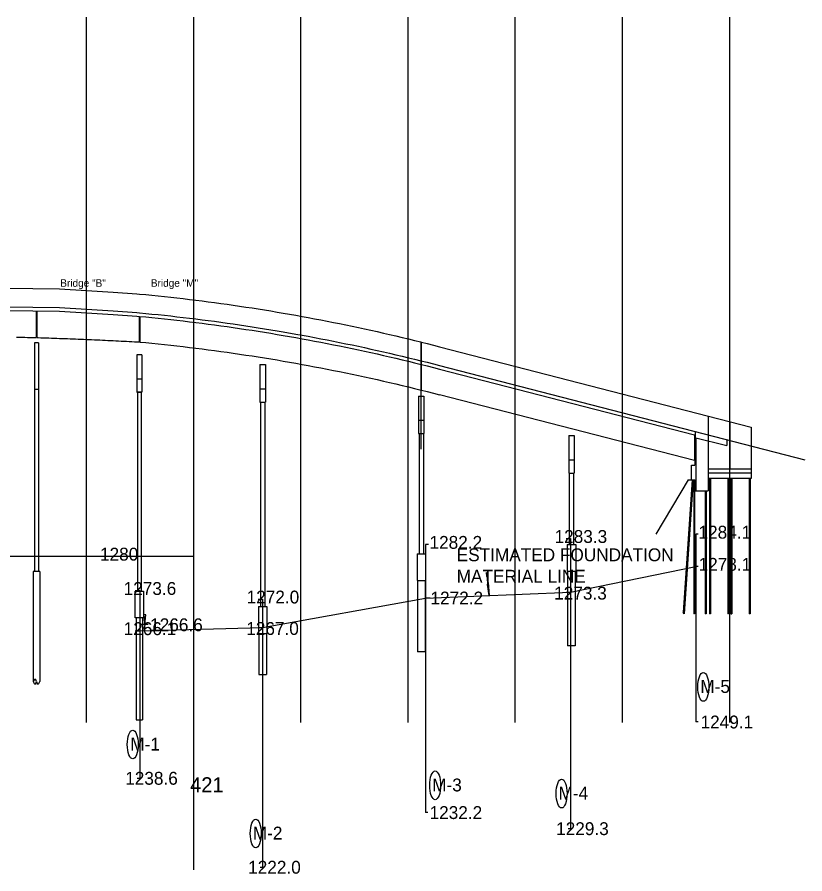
# Model space of a CAD drawing. Extents: x 2144454 to 2150191, y 137247 to 142100.
# Drawn here: x 2144990 to 2145724, y 137247 to 138047 of the extents above; entities that cross this region are included whole.
import ezdxf

# ---------------------------------------------------------------- set-up
doc = ezdxf.new("R2010")
doc.units = 0
for name, color, linetype in [('11', 7, 'Continuous'), ('3A', 7, 'Continuous'), ('BORE', 7, 'Continuous'), ('FinGrade', 7, 'Continuous'), ('PR_Align_Ramp_M_Txt', 7, 'Continuous'), ('PR_Bridge', 7, 'Continuous'), ('PR_Bridge_Pier', 7, 'Continuous'), ('PR_Bridge_Piling', 7, 'Continuous'), ('PR_Bridge_Slope_Wall', 7, 'Continuous'), ('T_BORE', 7, 'Continuous'), ('TOPO_Wall Retaining', 7, 'Continuous'), ('XSEC_Section_Grid_Major', 7, 'Continuous')]:
    doc.layers.add(name, color=color, linetype=linetype)

msp = doc.modelspace()

# ---------------------------------------------------------------- linework, layer by layer
at = {"layer": '11'}
for p, q in [((2145505.82, 137510.15), (2145622.49, 137534.15)), ((2145218.58, 137477.15), (2145370.38, 137504.65)), ((2145370.38, 137504.65), (2145505.82, 137510.15)), ((2145103.88, 137474.15), (2145218.58, 137477.15))]:
    msp.add_line(p, q, dxfattribs=at)
at = {"layer": '3A'}
msp.add_line((2145366.56, 137643.65), (2145366.56, 137711.69), dxfattribs=at)
at = {"layer": 'BORE'}
for p, q in [((2145501.53, 137560.15), (2145505.82, 137560.15)), ((2145505.82, 137560.15), (2145505.82, 137289.65)), ((2145624.76, 137564.15), (2145622.49, 137564.15)), ((2145622.49, 137564.15), (2145622.49, 137389.15)), ((2145370.38, 137554.65), (2145370.38, 137304.65)), ((2145373.36, 137554.65), (2145370.38, 137554.65)), ((2145370.38, 137554.65), (2145370.38, 137304.65)), ((2145624.76, 137534.15), (2145622.49, 137534.15)), ((2145099.59, 137511.65), (2145103.88, 137511.65)), ((2145103.88, 137511.65), (2145103.88, 137336.65)), ((2145374.67, 137504.65), (2145370.38, 137504.65)), ((2145501.53, 137510.15), (2145505.82, 137510.15)), ((2145214.29, 137503.65), (2145218.58, 137503.65)), ((2145218.58, 137503.65), (2145218.58, 137253.65)), ((2145099.59, 137474.15), (2145103.88, 137474.15)), ((2145214.29, 137477.15), (2145218.58, 137477.15)), ((2145624.89, 137389.15), (2145622.49, 137389.15)), ((2145101.48, 137336.65), (2145103.88, 137336.65)), ((2145372.78, 137304.65), (2145370.38, 137304.65)), ((2145372.78, 137304.65), (2145370.38, 137304.65)), ((2145372.78, 137304.65), (2145370.38, 137304.65)), ((2145503.42, 137289.65), (2145505.82, 137289.65)), ((2145216.18, 137253.65), (2145218.58, 137253.65))]:
    msp.add_line(p, q, dxfattribs=at)
at = {"layer": 'Defpoints'}
for p, q in [((2144454.23, 137543.65), (2145154.23, 137543.65)), ((2144999.91, 137543.65), (2145154.23, 137543.65)), ((2145154.23, 137391.15), (2145154.23, 137543.65)), ((2145154.23, 137251.15), (2145154.23, 137543.65)), ((2145111.85, 137480.13), (2145105.2, 137480.13)), ((2145110.19, 137476.69), (2145106.86, 137476.69))]:
    msp.add_line(p, q, dxfattribs=at)
msp.add_lwpolyline([(2145108.53, 137480.13), (2145109.57, 137489.14), (2145107.49, 137489.14)], close=True, dxfattribs=at)
at = {"layer": 'FinGrade'}
for p, q in [((2144979.23, 137776.3), (2145004.23, 137776.13)), ((2145004.23, 137776.13), (2145029.23, 137775.65)), ((2145029.23, 137775.65), (2145054.23, 137774.16)), ((2145054.23, 137774.16), (2145079.23, 137772.52)), ((2145079.23, 137772.52), (2145101.27, 137771.01)), ((2145101.27, 137771.01), (2145103.67, 137770.78)), ((2145383.67, 137721.65), (2145724.3, 137633.7))]:
    msp.add_line(p, q, dxfattribs=at)
msp.add_lwpolyline([(2145103.67, 137770.78), (2145109.51, 137770.23), (2145115.34, 137769.66), (2145121.17, 137769.07), (2145127.01, 137768.46), (2145132.84, 137767.83), (2145138.67, 137767.18), (2145144.51, 137766.51), (2145150.34, 137765.81), (2145156.17, 137765.1), (2145162.01, 137764.37), (2145167.84, 137763.62), (2145173.67, 137762.85), (2145179.51, 137762.05), (2145185.34, 137761.24), (2145191.17, 137760.41), (2145197.01, 137759.56), (2145202.84, 137758.68), (2145208.67, 137757.79), (2145214.51, 137756.88), (2145220.34, 137755.94), (2145226.17, 137754.99), (2145232.01, 137754.02), (2145237.84, 137753.02), (2145249.51, 137750.98), (2145255.34, 137749.92), (2145261.17, 137748.85), (2145267.01, 137747.76), (2145272.84, 137746.64), (2145278.67, 137745.51), (2145284.51, 137744.35), (2145290.34, 137743.18), (2145296.17, 137741.98), (2145302.01, 137740.77), (2145307.84, 137739.54), (2145313.67, 137738.28), (2145319.51, 137737.01), (2145325.34, 137735.71), (2145331.17, 137734.4), (2145337.01, 137733.06), (2145342.84, 137731.7), (2145348.67, 137730.33), (2145354.51, 137728.93), (2145360.34, 137727.52), (2145366.17, 137726.08), (2145372.01, 137724.63), (2145377.84, 137723.15), (2145383.67, 137721.65)], dxfattribs=at)
at = {"layer": 'PR_Bridge'}
for p, q in [((2144979.23, 137793.8), (2145004.23, 137793.63)), ((2145004.23, 137793.63), (2145029.23, 137793.15)), ((2145029.23, 137793.15), (2145054.23, 137791.66)), ((2145054.23, 137791.66), (2145079.23, 137790.02)), ((2145079.23, 137790.02), (2145101.27, 137788.51)), ((2145101.27, 137788.51), (2145103.67, 137788.28)), ((2144979.23, 137772.96), (2145004.23, 137772.79)), ((2145004.23, 137772.79), (2145029.23, 137772.32)), ((2145007.3, 137772.74), (2145007.3, 137747.68)), ((2145007.97, 137772.72), (2145007.97, 137747.66)), ((2145029.23, 137772.32), (2145054.23, 137770.83)), ((2145054.23, 137770.83), (2145079.23, 137769.18)), ((2145079.23, 137769.18), (2145101.27, 137767.67)), ((2145101.27, 137767.67), (2145103.67, 137767.45)), ((2145103.24, 137767.36), (2145103.24, 137743.58)), ((2145103.24, 137767.31), (2145103.24, 137743.57)), ((2145103.91, 137767.29), (2145103.91, 137743.51)), ((2145101.27, 137743.76), (2145103.24, 137743.57)), ((2145366.49, 137722.67), (2145366.49, 137743.5)), ((2145366.66, 137722.63), (2145366.66, 137743.46)), ((2145383.67, 137739.15), (2145674.23, 137664.13)), ((2145366.41, 137698.77), (2145366.41, 137722.69)), ((2145366.74, 137698.69), (2145366.74, 137722.61)), ((2145383.67, 137718.32), (2145621.23, 137656.98)), ((2145383.67, 137694.55), (2145621.23, 137633.21)), ((2145634.23, 137674.46), (2145634.23, 137656.96)), ((2145654.23, 137669.29), (2145654.23, 137651.79)), ((2145674.23, 137664.13), (2145674.23, 137646.63)), ((2145621.23, 137656.97), (2145621.23, 137633.21)), ((2145622.31, 137654.06), (2145622.31, 137660.03)), ((2145621.23, 137654.32), (2145651.57, 137647.06)), ((2145621.23, 137654.32), (2145622.31, 137654.06)), ((2145621.56, 137654.24), (2145621.56, 137628.56)), ((2145622.56, 137654), (2145622.56, 137604.86)), ((2145651.57, 137652.48), (2145651.57, 137647.06)), ((2145618.56, 137628.56), (2145621.56, 137628.56)), ((2145618.56, 137614.86), (2145618.56, 137628.56)), ((2145618.56, 137614.86), (2145621.56, 137614.86)), ((2145621.56, 137614.86), (2145621.56, 137604.86)), ((2145621.56, 137604.86), (2145622.56, 137604.86))]:
    msp.add_line(p, q, dxfattribs=at)
for points in [[(2145103.67, 137788.28), (2145109.51, 137787.73), (2145115.34, 137787.16), (2145121.17, 137786.57), (2145127.01, 137785.96), (2145132.84, 137785.33), (2145138.67, 137784.68), (2145144.51, 137784.01), (2145150.34, 137783.31), (2145156.17, 137782.6), (2145162.01, 137781.87), (2145167.84, 137781.12), (2145173.67, 137780.35), (2145179.51, 137779.55), (2145185.34, 137778.74), (2145191.17, 137777.91), (2145197.01, 137777.06), (2145202.84, 137776.18), (2145208.67, 137775.29), (2145214.51, 137774.38), (2145220.34, 137773.44), (2145226.17, 137772.49), (2145232.01, 137771.52), (2145237.84, 137770.52), (2145249.51, 137768.48), (2145255.34, 137767.42), (2145261.17, 137766.35), (2145267.01, 137765.26), (2145272.84, 137764.14), (2145278.67, 137763.01), (2145284.51, 137761.85), (2145290.34, 137760.68), (2145296.17, 137759.48), (2145302.01, 137758.27), (2145307.84, 137757.04), (2145313.67, 137755.78), (2145319.51, 137754.51), (2145325.34, 137753.21), (2145331.17, 137751.9), (2145337.01, 137750.56), (2145342.84, 137749.2), (2145348.67, 137747.83), (2145354.51, 137746.43), (2145360.34, 137745.02), (2145366.17, 137743.58), (2145366.49, 137743.5)], [(2145103.67, 137767.45), (2145109.51, 137766.9), (2145115.34, 137766.33), (2145121.17, 137765.74), (2145127.01, 137765.13), (2145132.84, 137764.5), (2145138.67, 137763.84), (2145144.51, 137763.17), (2145150.34, 137762.48), (2145156.17, 137761.77), (2145162.01, 137761.04), (2145167.84, 137760.28), (2145173.67, 137759.51), (2145179.51, 137758.72), (2145185.34, 137757.91), (2145191.17, 137757.08), (2145197.01, 137756.22), (2145202.84, 137755.35), (2145208.67, 137754.46), (2145214.51, 137753.54), (2145220.34, 137752.61), (2145226.17, 137751.66), (2145232.01, 137750.68), (2145237.84, 137749.69), (2145249.51, 137747.64), (2145255.34, 137746.59), (2145261.17, 137745.52), (2145267.01, 137744.42), (2145272.84, 137743.31), (2145278.67, 137742.17), (2145284.51, 137741.02), (2145290.34, 137739.85), (2145296.17, 137738.65), (2145302.01, 137737.44), (2145307.84, 137736.2), (2145313.67, 137734.95), (2145319.51, 137733.67), (2145325.34, 137732.38), (2145331.17, 137731.06), (2145337.01, 137729.73), (2145342.84, 137728.37), (2145348.67, 137727), (2145354.51, 137725.6), (2145360.34, 137724.18), (2145366.49, 137722.67)], [(2144989.1, 137748.15), (2144991.6, 137748.09), (2144994.1, 137748.03), (2144996.6, 137747.97), (2144999.1, 137747.9), (2145001.6, 137747.84), (2145004.1, 137747.77), (2145006.6, 137747.7), (2145007.3, 137747.68)], [(2145007.97, 137747.66), (2145009.09, 137747.63), (2145011.59, 137747.55), (2145014.09, 137747.48), (2145016.59, 137747.4), (2145019.09, 137747.32), (2145021.59, 137747.24), (2145024.09, 137747.16), (2145026.59, 137747.07), (2145029.09, 137746.98), (2145031.59, 137746.9), (2145034.09, 137746.8), (2145036.59, 137746.71), (2145039.08, 137746.62), (2145041.58, 137746.52), (2145044.08, 137746.42), (2145046.58, 137746.33), (2145049.08, 137746.22), (2145051.58, 137746.12), (2145054.08, 137746.02), (2145056.58, 137745.91), (2145059.08, 137745.8), (2145061.58, 137745.69), (2145064.08, 137745.58), (2145066.58, 137745.46), (2145069.08, 137745.35), (2145071.57, 137745.23), (2145074.07, 137745.11), (2145076.57, 137744.99), (2145079.07, 137744.86), (2145081.57, 137744.74), (2145084.07, 137744.61), (2145086.57, 137744.48), (2145089.07, 137744.35), (2145091.57, 137744.22), (2145094.07, 137744.08), (2145096.57, 137743.95), (2145099.07, 137743.81), (2145101.56, 137743.67), (2145103.24, 137743.57)], [(2145102.42, 137743.65), (2145103.24, 137743.58)], [(2145103.91, 137743.51), (2145109.51, 137742.98), (2145115.34, 137742.41), (2145121.17, 137741.82), (2145127.01, 137741.21), (2145132.84, 137740.58), (2145138.67, 137739.93), (2145144.51, 137739.26), (2145150.34, 137738.56), (2145156.17, 137737.85), (2145162.01, 137737.12), (2145167.84, 137736.37), (2145173.67, 137735.6), (2145179.51, 137734.8), (2145185.34, 137733.99), (2145191.17, 137733.16), (2145197.01, 137732.31), (2145202.84, 137731.43), (2145208.67, 137730.54), (2145214.51, 137729.63), (2145220.34, 137728.69), (2145226.17, 137727.74), (2145232.01, 137726.77), (2145237.84, 137725.77), (2145249.51, 137723.73), (2145255.34, 137722.67), (2145261.17, 137721.6), (2145267.01, 137720.51), (2145272.84, 137719.39), (2145278.67, 137718.26), (2145284.51, 137717.1), (2145290.34, 137715.93), (2145296.17, 137714.73), (2145302.01, 137713.52), (2145307.84, 137712.29), (2145313.67, 137711.03), (2145319.51, 137709.76), (2145325.34, 137708.46), (2145331.17, 137707.15), (2145337.01, 137705.81), (2145342.84, 137704.45), (2145348.67, 137703.08), (2145354.51, 137701.68), (2145360.34, 137700.27), (2145366.41, 137698.77)], [(2145366.66, 137743.46), (2145372.01, 137742.13), (2145377.84, 137740.65), (2145383.67, 137739.15)], [(2145366.66, 137722.63), (2145372.01, 137721.29), (2145377.84, 137719.82), (2145383.67, 137718.32)], [(2145366.74, 137698.69), (2145372.01, 137697.38), (2145377.84, 137695.9), (2145383.67, 137694.4)]]:
    msp.add_lwpolyline(points, dxfattribs=at)
at = {"layer": 'PR_Bridge_Pier'}
for p, q in [((2145009.64, 137742.69), (2145005.64, 137742.69)), ((2145005.64, 137742.69), (2145005.64, 137529.3)), ((2145009.64, 137742.69), (2145009.64, 137529.3)), ((2145105.83, 137731.66), (2145101.33, 137731.66)), ((2145101.33, 137731.66), (2145101.33, 137709.16)), ((2145105.83, 137731.66), (2145105.83, 137709.16)), ((2145216.08, 137722.43), (2145216.08, 137699.93)), ((2145216.08, 137722.43), (2145221.08, 137722.43)), ((2145221.08, 137722.43), (2145221.08, 137699.93)), ((2145101.33, 137709.16), (2145101.33, 137696.66)), ((2145101.33, 137709.16), (2145105.83, 137709.16)), ((2145105.83, 137709.16), (2145105.83, 137696.66)), ((2145009.64, 137699.13), (2145005.64, 137699.13)), ((2145101.33, 137696.66), (2145105.83, 137696.66)), ((2145105.59, 137696.66), (2145101.57, 137696.66)), ((2145101.83, 137696.66), (2145101.83, 137511.15)), ((2145105.33, 137696.66), (2145105.33, 137511.15)), ((2145216.08, 137699.93), (2145216.08, 137687.43)), ((2145216.08, 137699.93), (2145221.08, 137699.93)), ((2145221.08, 137699.93), (2145221.08, 137687.43)), ((2145364.06, 137693.17), (2145369.06, 137693.17)), ((2145364.06, 137693.17), (2145364.06, 137670.67)), ((2145369.06, 137693.17), (2145369.06, 137670.67)), ((2145216.08, 137687.43), (2145221.08, 137687.43)), ((2145216.58, 137687.43), (2145216.58, 137496.64)), ((2145220.58, 137687.43), (2145220.58, 137496.64)), ((2145364.06, 137670.67), (2145369.06, 137670.67)), ((2145364.06, 137670.67), (2145364.06, 137658.17)), ((2145369.06, 137670.67), (2145369.06, 137658.17)), ((2145364.06, 137658.17), (2145369.06, 137658.17)), ((2145364.56, 137658.17), (2145364.56, 137546.01)), ((2145368.56, 137658.17), (2145368.56, 137546.01)), ((2145504.06, 137656.26), (2145509.06, 137656.26)), ((2145504.06, 137656.26), (2145504.06, 137633.76)), ((2145509.06, 137656.26), (2145509.06, 137633.76)), ((2145504.06, 137633.76), (2145509.06, 137633.76)), ((2145504.06, 137633.76), (2145504.06, 137621.26)), ((2145509.06, 137633.76), (2145509.06, 137621.26)), ((2145504.06, 137621.26), (2145509.06, 137621.26)), ((2145504.56, 137621.26), (2145504.56, 137554.66)), ((2145508.56, 137621.26), (2145508.56, 137554.66)), ((2145502.56, 137554.66), (2145510.56, 137554.66)), ((2145502.56, 137554.66), (2145502.56, 137529.66)), ((2145510.56, 137554.66), (2145510.56, 137529.66)), ((2145362.56, 137546.01), (2145370.56, 137546.01)), ((2145362.56, 137546.01), (2145362.56, 137521.01)), ((2145370.56, 137546.01), (2145370.56, 137521.01)), ((2145004.64, 137529.3), (2145004.64, 137426.7)), ((2145010.64, 137529.3), (2145004.64, 137529.3)), ((2145010.64, 137529.3), (2145010.64, 137426.7)), ((2145502.56, 137529.66), (2145510.56, 137529.66)), ((2145503.06, 137529.66), (2145503.06, 137460.15)), ((2145510.06, 137529.66), (2145510.06, 137460.15)), ((2145362.56, 137521.01), (2145370.56, 137521.01)), ((2145363.06, 137521.01), (2145363.06, 137454.65)), ((2145370.06, 137521.01), (2145370.06, 137454.65)), ((2145214.58, 137496.64), (2145222.58, 137496.64)), ((2145214.58, 137496.64), (2145214.58, 137471.64)), ((2145222.58, 137496.64), (2145222.58, 137471.64)), ((2145100.57, 137486.15), (2145100.57, 137391.15)), ((2145106.59, 137486.15), (2145106.59, 137391.15)), ((2145214.58, 137471.64), (2145222.58, 137471.64)), ((2145215.08, 137471.64), (2145215.08, 137433.44)), ((2145222.08, 137471.64), (2145222.08, 137433.44)), ((2145510.06, 137460.15), (2145503.06, 137460.15)), ((2145370.06, 137454.65), (2145363.06, 137454.65)), ((2145215.08, 137433.44), (2145222.08, 137433.44)), ((2145100.57, 137391.15), (2145106.59, 137391.15))]:
    msp.add_line(p, q, dxfattribs=at)
msp.add_lwpolyline([(2145103.58, 137511.15), (2145107.58, 137511.15), (2145107.58, 137486.15), (2145099.58, 137486.15), (2145099.58, 137511.15)], close=True, dxfattribs=at)
for centre, major_axis, start_param, end_param in [((2145006.14, 137415.82), (0, 13.23), 5.678607, 6.887764), ((2145006.14, 137437.59), (0, 13.23), 2.537014, 3.746171), ((2145009.14, 137437.47), (0, 13.11), 2.534234, 3.748951)]:
    msp.add_ellipse(centre, major_axis=major_axis, ratio=0.2, start_param=start_param, end_param=end_param, dxfattribs=at)
at = {"layer": 'PR_Bridge_Piling'}
for p, q in [((2145619.12, 137614.86), (2145610.88, 137491.17)), ((2145620, 137614.86), (2145611.67, 137489.86)), ((2145620.65, 137614.86), (2145620.65, 137489.86)), ((2145621.48, 137614.86), (2145621.48, 137489.86)), ((2145611.67, 137489.86), (2145610.88, 137491.17)), ((2145621.48, 137489.86), (2145620.65, 137489.86))]:
    msp.add_line(p, q, dxfattribs=at)
at = {"layer": 'PR_Bridge_Slope_Wall'}
for q in [(2145585.23, 137564.3), (2145618.56, 137614.86)]:
    msp.add_line((2145615.56, 137614.86), q, dxfattribs=at)
at = {"layer": 'T_BORE'}
msp.add_lwpolyline([(2145429.04, 137519.17), (2145429.78, 137507.05), (2145428.29, 137517.31)], close=True, dxfattribs=at)
for centre in [(2145629.59, 137421.77), (2145097.43, 137368.02), (2145379.46, 137329.92), (2145379.46, 137329.92), (2145379.46, 137329.92), (2145497.38, 137322.27), (2145212.13, 137285.02)]:
    msp.add_ellipse(centre, major_axis=(0, -13.44), ratio=0.379178, dxfattribs=at)
msp.add_open_spline([(2145428.67, 137518.24), (2145427.35, 137531.42), (2145426.48, 137526.33), (2145428.01, 137524.83), (2145427.1, 137525)], degree=3, dxfattribs=at)
at = {"layer": 'TOPO_Wall Retaining'}
for p, q in [((2145634.23, 137656.96), (2145634.23, 137604.86)), ((2145654.23, 137651.79), (2145654.23, 137625.05)), ((2145674.23, 137646.63), (2145674.23, 137616.26)), ((2145674.28, 137625.05), (2145634.23, 137625.05)), ((2145674.28, 137621.26), (2145634.23, 137621.26)), ((2145674.28, 137616.26), (2145634.23, 137616.26)), ((2145635.32, 137616.26), (2145635.32, 137489.86)), ((2145636.15, 137616.26), (2145636.15, 137489.86)), ((2145652.32, 137616.26), (2145652.32, 137489.86)), ((2145653.15, 137616.26), (2145653.15, 137489.86)), ((2145655.32, 137616.26), (2145655.32, 137489.86)), ((2145656.15, 137616.26), (2145656.15, 137489.86)), ((2145672.32, 137616.26), (2145672.32, 137489.86)), ((2145673.15, 137616.26), (2145673.15, 137489.86)), ((2145622.56, 137604.86), (2145634.23, 137604.86)), ((2145631.4, 137604.86), (2145631.4, 137489.86)), ((2145632.23, 137604.86), (2145632.23, 137489.86)), ((2145632.23, 137489.86), (2145631.4, 137489.86)), ((2145636.15, 137489.86), (2145635.32, 137489.86)), ((2145653.15, 137489.86), (2145652.32, 137489.86)), ((2145655.32, 137489.86), (2145656.15, 137489.86)), ((2145673.15, 137489.86), (2145672.32, 137489.86))]:
    msp.add_line(p, q, dxfattribs=at)
at = {"layer": 'XSEC_Section_Grid_Major'}
for p, q in [((2145054.23, 137388.65), (2145054.23, 138046.65)), ((2145154.23, 137388.65), (2145154.23, 138046.65)), ((2145254.23, 137388.65), (2145254.23, 138046.65)), ((2145354.23, 137388.65), (2145354.23, 138046.65)), ((2145454.23, 137388.65), (2145454.23, 138046.65)), ((2145554.23, 137388.65), (2145554.23, 138046.65)), ((2145654.23, 137388.65), (2145654.23, 138046.65))]:
    msp.add_line(p, q, dxfattribs=at)

# ---------------------------------------------------------------- texts
at = {"layer": 'Defpoints'}
for s, height, p in [('1280', 12, (2145066.86, 137539.62)), ('1266.6', 12, (2145113.61, 137473.74)), ('421', 14, (2145150.92, 137323.51))]:
    msp.add_text(s, height=height, dxfattribs=at).set_placement(p)
at = {"layer": 'PR_Align_Ramp_M_Txt'}
for s, p in [('Bridge "B"', (2145029.8, 137795.08)), ('Bridge "M"', (2145114.3, 137795.08))]:
    msp.add_text(s, height=7, dxfattribs=at).set_placement(p)
at = {"layer": 'T_BORE'}
for s, p in [('1283.3', (2145490.84, 137556.11)), ('ESTIMATED FOUNDATION ', (2145399.55, 137539.02)), ('MATERIAL LINE', (2145399.55, 137519.02)), ('1273.6', (2145088.91, 137507.61)), ('1273.3', (2145490.48, 137503.27)), ('1272.0', (2145203.6, 137499.61)), ('1266.1', (2145088.91, 137470.11)), ('1267.0', (2145203.24, 137470.27)), ('M-5', (2145626.82, 137416.15)), ('M-1', (2145095.13, 137362.4)), ('1238.6', (2145090.36, 137330.52)), ('M-3', (2145376.66, 137324.29)), ('M-3', (2145376.66, 137324.29)), ('M-3', (2145376.66, 137324.29)), ('M-4', (2145494.52, 137316.65)), ('M-2', (2145209.39, 137279.4)), ('1229.3', (2145492.3, 137283.52)), ('1222.0', (2145205.05, 137247.52))]:
    msp.add_text(s, height=12, dxfattribs=at).set_placement(p)
for s, rotation, p in [('1284.1', 0, (2145625.1, 137560.11)), ('1282.2', 0, (2145374.2, 137550.61)), ('1278.1', 0, (2145625.18, 137530.11)), ('1272.2', 360, (2145375.1, 137498.69)), ('1249.1', 0, (2145627.01, 137383.02)), ('1232.2', 360, (2145374.25, 137298.52)), ('1232.2', 360, (2145374.25, 137298.52))]:
    msp.add_text(s, height=12, rotation=rotation, dxfattribs=at).set_placement(p)

doc.saveas('drawing.dxf')
